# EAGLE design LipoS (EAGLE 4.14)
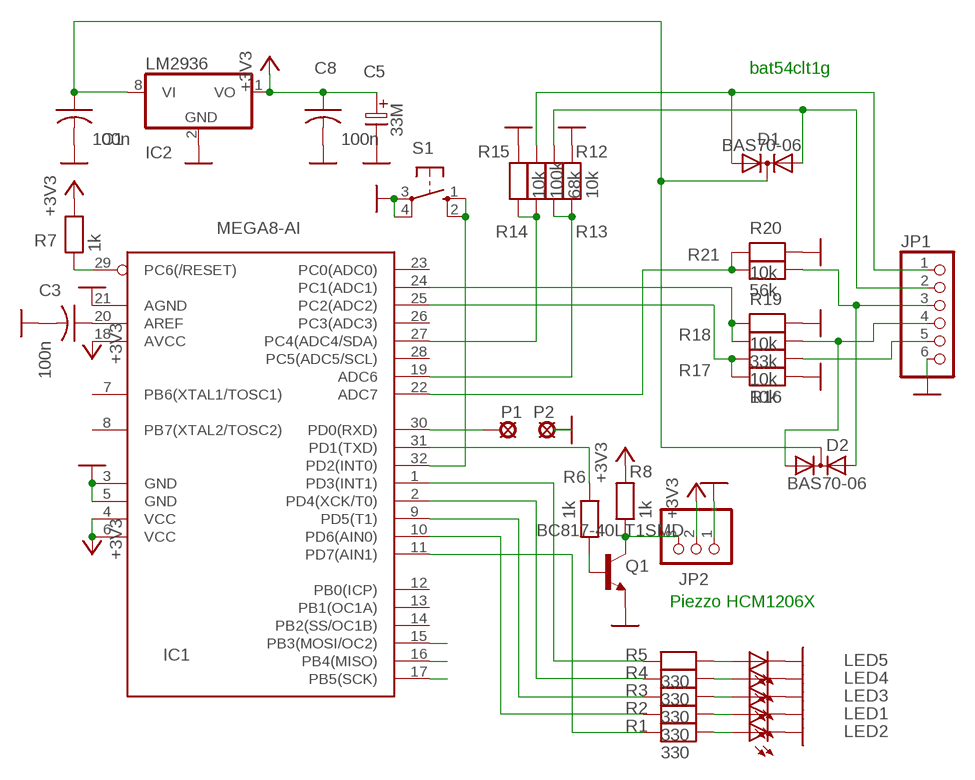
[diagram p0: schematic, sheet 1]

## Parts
C1  100n  CAP-50805  [C0805K]
C3  100n  CAP-50805  [C0805K]
C5  33M  ELC-2,5  [CAP_B]
C8  100n  CAP-50805  [C0805K]
D1  BAS70-06  [SOT23]
D2  BAS70-06  [SOT23]
IC1  MEGA8-AI  [TQFP32-08]
IC2  LM2936  LM2931  [SO08]
JP1  PINHD-1X6  [1X06]
JP2  PINHD-1X3  [1X03]
LED1  LEDCHIPLED_0805  [CHIPLED_0805]
LED2  LEDCHIPLED_0805  [CHIPLED_0805]
LED3  LEDCHIPLED_0805  [CHIPLED_0805]
LED4  LEDCHIPLED_0805  [CHIPLED_0805]
LED5  LEDCHIPLED_0805  [CHIPLED_0805]
P1  SMD  [SMD]
P2  SMD  [SMD]
Q1  BC817-40LT1SMD  [SOT23-BEC]
R1  330  RESEU-7,50805  [C0805K]
R2  330  RESEU-7,50805  [C0805K]
R3  330  RESEU-7,50805  [C0805K]
R4  330  RESEU-7,50805  [C0805K]
R5  330  RESEU-7,50805  [C0805K]
R6  1k  RESEU-7,50805  [C0805K]
R7  1k  RESEU-7,50805  [C0805K]
R8  1k  RESEU-7,50805  [C0805K]
R12  10k  RESEU-7,50805  [C0805K]
R13  68k  RESEU-7,50805  [C0805K]
R14  100k  RESEU-7,50805  [C0805K]
R15  10k  RESEU-7,50805  [C0805K]
R16  10k  RESEU-7,50805  [C0805K]
R17  10k  RESEU-7,50805  [C0805K]
R18  33k  RESEU-7,50805  [C0805K]
R19  10k  RESEU-7,50805  [C0805K]
R20  10k  RESEU-7,50805  [C0805K]
R21  56k  RESEU-7,50805  [C0805K]
S1  10-XX  [B3F-10XX]

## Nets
+3V3: C5.1 C8.1 IC1.4(VCC) IC1.6(VCC) IC1.18(AVCC) IC2.1(VO) JP2.2 R7.2 R8.2
GND: C1.2 C3.2 C5.2 C8.2 IC1.3(GND) IC1.5(GND) IC1.21(AGND) IC2.2(GND) JP1.6 JP2.1 LED1.C LED2.C LED3.C LED4.C LED5.C P2.1(MP) Q1.E R12.2 R15.2 R16.2 R19.2 R20.2 S1.3(P) S1.4(P1)
MISO: IC1.16(PB4(MISO))
MOSI: IC1.15(PB3(MOSI/OC2))
N$1: LED1.A R2.2
N$3: IC1.2(PD4(XCK/T0)) R4.1
N$4: LED3.A R3.2
N$5: LED2.A R1.2
N$6: LED4.A R4.2
N$7: LED5.A R5.2
N$8: IC1.9(PD5(T1)) R3.1
N$9: IC1.10(PD6(AIN0)) R2.1
N$10: C3.1 IC1.20(AREF)
N$11: IC1.11(PD7(AIN1)) R1.1
N$12: JP2.3 Q1.C R8.1
N$13: Q1.B R6.2
N$35: IC1.32(PD2(INT0)) S1.1(S) S1.2(S1)
P1: IC1.1(PD3(INT1)) R5.1
RST: IC1.29(PC6(/RESET)) R7.1
RXD: IC1.30(PD0(RXD)) P1.1(MP)
SCK: IC1.17(PB5(SCK))
TXD: IC1.31(PD1(TXD)) R6.1
U1: JP1.5 R17.2
U2: D2.1(A1) JP1.4 R18.2
U3: D2.2(A2) JP1.3 R21.2
U4: D1.1(A1) JP1.2 R13.2
U5: D1.2(A2) JP1.1 R14.2
UD1: IC1.25(PC2(ADC2)) R16.1 R17.1
UD2: IC1.24(PC1(ADC1)) R18.1 R19.1
UD3: IC1.22(ADC7) R20.1 R21.1
UD4: IC1.19(ADC6) R12.1 R13.1
UD5: IC1.27(PC4(ADC4/SDA)) R14.1 R15.1
VIN: C1.1 D1.3(C) D2.3(C) IC2.8(VI)
Unconnected: IC1.7(PB6(XTAL1/TOSC1)) IC1.8(PB7(XTAL2/TOSC2)) IC1.12(PB0(ICP)) IC1.13(PB1(OC1A)) IC1.14(PB2(SS/OC1B)) IC1.23(PC0(ADC0)) IC1.26(PC3(ADC3)) IC1.28(PC5(ADC5/SCL))

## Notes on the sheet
- bat54clt1g
- Piezzo HCM1206X

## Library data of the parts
C1 C3 C8 = discrete:CAP-5
C5 = discrete:ELC-2,5
D1 D2 = diode:BAS70-06: Silicon Schottky Diodes General-purpose diode for high-speed switching
IC1 = avr:MEGA8: MICROCONTROLLER 8 Kbytes FLASH 1 kbytes SRAM 512 bytes EEPROM USART 6-channel 10 bit ADC 2-channel 8 bit ADC
IC2 = linear:LM2931
JP1 = pinhead:PINHD-1X6: PIN HEADER
JP2 = pinhead:PINHD-1X3: PIN HEADER
LED1-LED5 = led:LED: LED
P1 P2 = solpad:SMD
Q1 = transistor-npn:BC817*: NPN Transistor
R1-R8 R12-R21 = discrete:RESEU-7,5
S1 = switch-omron:10-XX: OMRON SWITCH

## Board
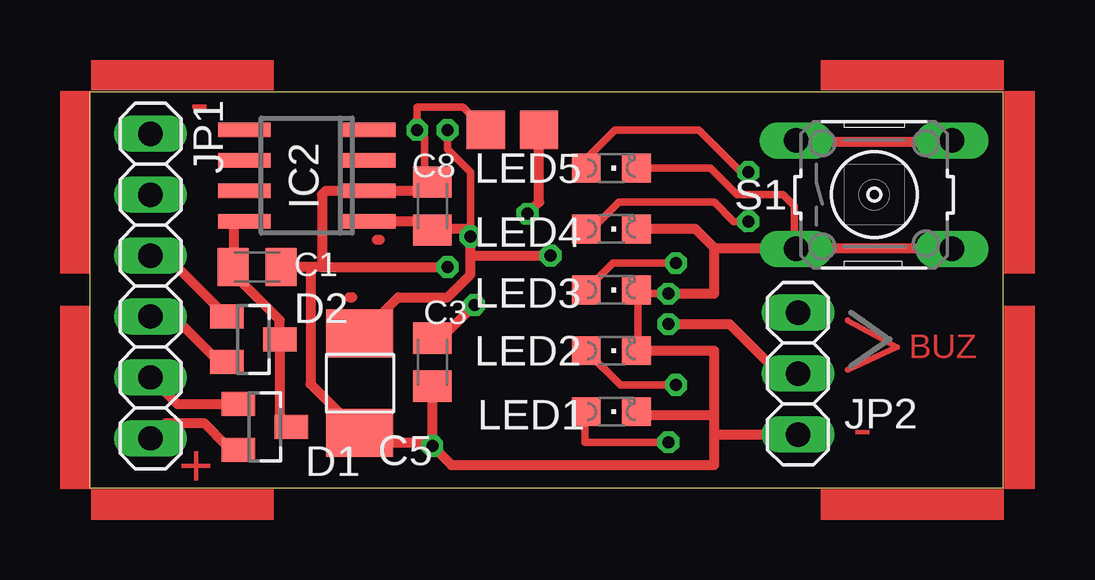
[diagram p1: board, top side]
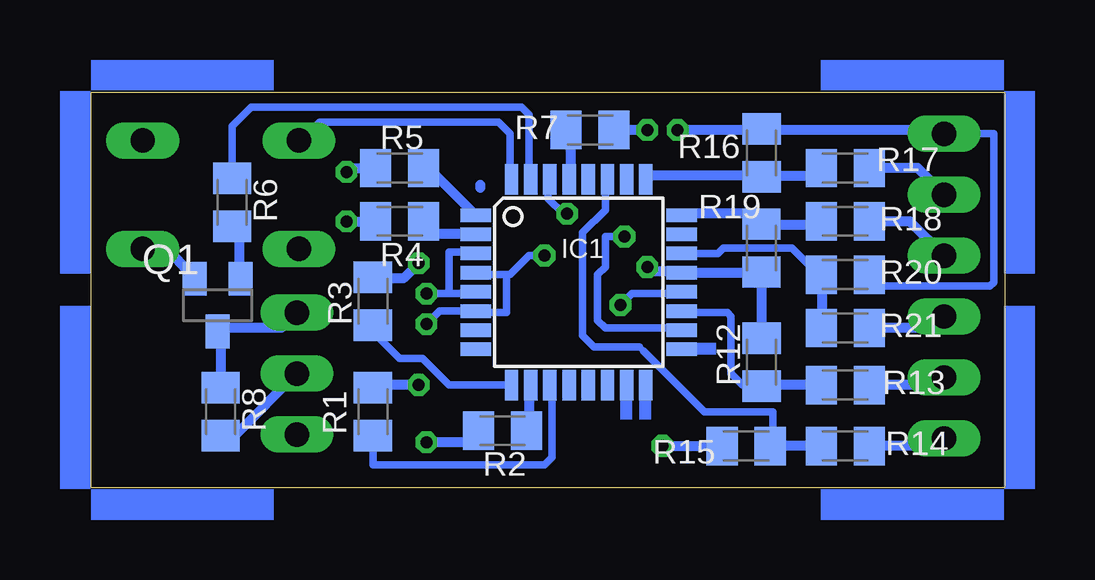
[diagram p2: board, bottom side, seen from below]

Size 38.09 x 16.5 mm. Coordinates in mm from the lower left corner, seen from the top.
Outline: 0,0 38.09,0 38.09,16.5 0,16.5 0,0
Copper layers (1*16): Top 0.035mm / dielectric 1.5mm / Bottom 0.035mm
Design rules "default": minimum track width 10mil, minimum drill 24mil, track to track 8mil, track to pad 8mil, pad to pad 8mil, via to via 8mil, smd to smd 8mil, copper to edge 40mil, drill to drill 8mil, minimum pad ring 10mil, minimum via ring 8mil, stop-mask expansion 0mil, vias tented up to drill 0mil, thermal gap 10mil

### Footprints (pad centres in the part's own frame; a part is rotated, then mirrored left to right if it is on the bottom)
C0805K = smd 1.3 x 1.6: 1 -1,0; 2 1,0
CAP_B = smd 2 x 2.8: 1 -2.155,-0.498; 2 1.998,-0.498
SOT23 = smd 1 x 1.4: 1 -0.95,-1.1; 2 0.95,-1.1; 3 0,1.1
TQFP32-08 = smd 1.27 x 0.559: 1 -4.293,2.8; 2 -4.293,2; 3 -4.293,1.2; 4 -4.293,0.4; 5 -4.293,-0.4; 6 -4.293,-1.2; 7 -4.293,-2; 8 -4.293,-2.8; 17 4.293,-2.8; 18 4.293,-2; 19 4.293,-1.2; 20 4.293,-0.4; 21 4.293,0.4; 22 4.293,1.2; 23 4.293,2; 24 4.293,2.8 | smd 0.559 x 1.27: 9 -2.8,-4.293; 10 -2,-4.293; 11 -1.2,-4.293; 12 -0.4,-4.293; 13 0.4,-4.293; 14 1.2,-4.293; 15 2,-4.293; 16 2.8,-4.293; 25 2.8,4.293; 26 2,4.293; 27 1.2,4.293; 28 0.4,4.293; 29 -0.4,4.293; 30 -1.2,4.293; 31 -2,4.293; 32 -2.8,4.293
SO08 = smd 0.6 x 2.2: 1 -1.905,-2.6; 2 -0.635,-2.6; 3 0.635,-2.6; 4 1.905,-2.6; 5 1.905,2.6; 6 0.635,2.6; 7 -0.635,2.6; 8 -1.905,2.6
1X06 = drill 1.016 long: 1 -6.35,0; 2 -3.81,0; 3 -1.27,0; 4 1.27,0; 5 3.81,0; 6 6.35,0
1X03 = drill 1.016 long: 1 -2.54,0; 2 0,0; 3 2.54,0
CHIPLED_0805 = smd 1.2 x 1.2: A 0,-1.05; C 0,1.05
SMD = smd 1.6 x 1.6: 1 0,0
SOT23-BEC = smd 1 x 1.4: B -0.95,-1.1; C 0,1.1; E 0.95,-1.1
B3F-10XX = drill 1.016 long: 1 -3.251,2.261; 2 3.251,2.261; 3 -3.251,-2.261; 4 3.251,-2.261

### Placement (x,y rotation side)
C1  6.98,9.2 0 top
C3  14.28,5.23 270 top
C5  11.74,4.28 270 top
C8  14.28,11.74 90 top
D1  7.3,2.54 270 top
D2  6.82,6.19 270 top
IC1  17.77,8.57 0 bottom
IC2  9.04,13.01 90 top
JP1  2.53,8.41 90 top
JP2  29.52,4.76 90 top
LED1  21.74,3.17 270 top
LED2  21.74,5.71 270 top
LED3  21.74,8.25 270 top
LED4  21.74,10.79 270 top
LED5  21.74,13.33 270 top
P1  18.73,14.92 90 top
P2  16.5,14.92 0 top
Q1  32.82,7.62 180 bottom
R1  26.35,3.17 90 bottom
R2  20.95,2.38 180 bottom
R3  26.35,7.77 90 bottom
R4  25.23,11.11 180 bottom
R5  25.23,13.33 180 bottom
R6  32.22,11.9 270 bottom
R7  17.3,14.92 0 bottom
R8  32.7,3.17 270 bottom
R12  10.15,5.23 90 bottom
R13  6.66,4.28 0 bottom
R14  6.66,1.74 0 bottom
R15  10.79,1.74 180 bottom
R16  10.15,13.96 90 bottom
R17  6.66,13.33 0 bottom
R18  6.66,11.11 0 bottom
R19  10.15,10 270 bottom
R20  6.66,8.89 0 bottom
R21  6.66,6.66 0 bottom
S1  32.7,12.22 0 top
U$9  [ANGLE-NE1-16]  38.13,16.57 0 top
U$10  [ANGLE-NE1-16]  0.03,16.57 90 top
U$12  [ANGLE-NE1-16]  0.03,-0.07 180 top
U$13  [ANGLE-NE1-16]  38.13,-0.07 270 top

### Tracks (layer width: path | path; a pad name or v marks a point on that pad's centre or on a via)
+3V3  (via drill 0.5)
  Top 0.305: v14.92,14.92 14.92,14.12 15.87,13.17 15.87,10.79 v15.87,10.47 | 14.33,10.79 C8.1 14.12,10.9 14.12,11.11 | C5.1 11.36,6.44 | JP2.2
  Top 0.406: 15.87,9.68 15.87,8.88 14.92,7.93 12.85,7.93 11.36,6.44 | 15.87,9.68 v15.87,10.47 | v24.12,6.82 26.66,6.82 28.73,4.76 JP2.2 | 15.87,9.68 v19.2,9.68 | 15.87,10.79 14.33,10.79 | 14.12,11.11 IC2.1
  Bottom 0.254: 22,7.3 IC1.6 | IC1.4 22.06,9.04
  Bottom 0.305: IC1.18 13.58,6.66 16.66,6.66 16.98,6.98 16.98,8.88 16.66,9.2 16.66,10.47 v15.87,10.47 | R8.2 32.7,2.22 32.06,2.22 | IC1.6 23.58,7.37 v24.12,6.82 | 22,7.3 20.79,7.3 20.79,8.88 | 20.79,8.88 21.9,8.88 21.9,8.97 IC1.4 22.07,8.89 22.06,8.88 IC1.4 | 20.79,8.88 20.63,8.88 19.84,9.68 v19.2,9.68 | R7.2
  Bottom 0.406: JP2.2 32.06,2.22 | v14.92,14.92 R7.2
GND  (via drill 0.5)
  Top 0.305: LED5.C 25.87,13.33 26.98,12.22 28.89,12.22 29.36,11.74 29.36,10 | LED2.C 22.85,5.71 22.85,8.19 LED3.C | LED2.C | LED3.C 22.95,8.09 v24.12,8.09 22.7,8.09 22.7,8.15 LED3.C | 22.85,3.01 22.85,3.11 LED1.C | 11.58,1.9 11.58,1.94 C5.2 | 14.12,1.9 v14.28,1.74 | 14.28,4.55 C3.2 | 29.36,10 29.41,10 S1.3 | 36.03,10 35.99,10 S1.4 | S1.3 29.48,10 | 26.03,3.01 26.03,2.22 | IC2.2 11.42,12.38 | P2.1 15.55,15.87 13.65,15.87 v13.65,14.92 13.96,14.6 13.96,12.85 14.17,12.85 C8.2 13.96,12.43 13.96,12.38 | 29.36,10 29.4,9.96 S1.3 | LED4.C | JP2.1 | C1.2
  Top 0.406: 22.85,5.71 26.03,5.71 26.03,3.01 | 26.03,3.01 22.85,3.01 | 11.58,1.9 14.12,1.9 | 14.28,4.55 v14.28,1.74 15.08,0.95 26.03,0.95 26.03,3.01 | 29.48,10 35.99,10 | 26.03,2.22 JP2.1 | 9.2,9.2 C1.2 | 9.68,9.2 9.2,9.2 | 9.68,9.2 v14.92,9.2 | C5.2 9.2,4.33 9.2,9.2 | 26.03,10 29.36,10 | LED4.C 25.24,10.79 26.03,10 | 26.03,10 26.03,8.09 v24.12,8.09 | 13.96,12.38 IC2.2 9.84,12.38 9.68,12.22 9.68,9.2
  Bottom 0.305: 10.15,14.92 R16.2 | JP1.6 2.69,14.92 | R20.2 5.19,8.41 0.63,8.41 0.47,8.57 0.47,14.76 JP1.6 | JP1.6 | v24.12,8.09 23.17,8.09 | 23.17,8.09 22.14,8.09 IC1.5 22.06,8.16 22.06,8.09 23.17,8.09 | IC1.3 22.14,9.84 23.17,9.84 23.17,8.09 | R15.2 | 36.03,10 35.99,10 S1.4 | 10.15,6.19 R12.2 | 10.15,6.19 | R19.2 10.2,9 10.31,8.88 10.4,8.97 | 13.49,9.04 IC1.21 | v14.92,9.2 14.76,9.04
  Bottom 0.406: 2.69,14.92 10.15,14.92 v13.65,14.92 | v14.28,1.74 R15.2 | Q1.E 34.93,10 35.99,10 | R19.2 10.15,6.19 | IC1.21 10.4,8.97 | 14.76,9.04 13.49,9.04
N$1  (via drill 0.5)
  Top 0.305: v24.12,1.9 20.63,1.9 20.63,3.11 LED1.A
  Bottom 0.305: R2.2 22.43,1.9
  Bottom 0.406: 22.43,1.9 v24.12,1.9
N$2
  Bottom 0.406: 21.87,12.5 21.87,12.63
N$3
  Bottom 0.406: R4.1 24.23,10.9 23.9,10.57 IC1.2
N$4  (via drill 0.5)
  Top 0.305: LED3.A 21.8,9.36 v24.44,9.36
  Bottom 0.305: 26.35,8.73 R3.2 | R3.2
  Bottom 0.406: v24.44,9.36 25.08,8.73 26.35,8.73
N$5  (via drill 0.5)
  Top 0.305: LED2.A 22.12,4.28 v24.44,4.28
  Bottom 0.305: 26.35,4.28 R1.2 | R1.2
  Bottom 0.406: v24.44,4.28 26.35,4.28
N$6  (via drill 0.5)
  Top 0.305: LED4.A 20.79,10.89 20.79,10.95 21.11,10.95 22.06,11.9 26.03,11.9 26.82,11.11 v27.46,11.11
  Bottom 0.305: R4.2
  Bottom 0.406: v27.46,11.11 R4.2
N$7  (via drill 0.5)
  Top 0.305: LED5.A 20.69,13.71 21.9,14.92 25.39,14.92 27.14,13.17 v27.46,13.17
  Bottom 0.305: R5.2 26.19,13.33 | R5.2 | v27.46,13.17 27.3,13.33
  Bottom 0.406: 27.3,13.33 R5.2
N$8
  Bottom 0.305: IC1.9 23.17,4.28 24.28,5.39 25.24,5.39 26.35,6.5 R3.1
N$9
  Bottom 0.305: 19.84,4.28 IC1.10 | 19.84,2.49 R2.1
  Bottom 0.406: 19.84,4.28 19.84,2.49
N$10  (via drill 0.5)
  Top 0.305: C3.1 14.65,6.23
  Top 0.406: 14.65,6.23 v16.03,7.61
  Bottom 0.305: IC1.20 13.56,8.09 15.55,8.09 v16.03,7.61
N$11
  Bottom 0.305: IC1.11 18.89,4.19 18.89,1.26 19.2,0.95 26.35,0.95 R1.1 | R1.1 26.35,2.38 | R1.1
N$12
  Bottom 0.305: 32.55,6.66 Q1.C 32.7,6.51 | R8.1 32.7,4.12
  Bottom 0.406: JP2.3 30.16,6.66 32.55,6.66 | 32.7,6.51 R8.1
N$13
  Bottom 0.305: 31.9,8.73 31.76,8.73 Q1.B | 31.9,10.58 R6.2
  Bottom 0.406: 31.9,8.73 31.9,10.58
N$16
  Top 0.254: 31.58,6.98 33.65,5.87 31.58,4.92
N$17
  Top 0.406: 11.96,10.35 12.09,10.35
N$18
  Top 0.406: 10.82,7.93 10.95,7.93
N$35
  Top 0.305: 36.03,14.44 35.99,14.44 S1.2 | S1.1 29.48,14.44
  Top 0.406: 29.48,14.44 35.99,14.44
  Bottom 0.305: IC1.32 20.63,12.92 20.63,14.76 21.11,15.24 28.57,15.24 29.2,14.6 29.36,14.6 29.36,14.56 S1.1
P1
  Bottom 0.305: R5.1 | 24.03,13.33 R5.1
  Bottom 0.406: IC1.1 24.03,13.33
RST
  Bottom 0.305: 18.09,14.65 R7.1 | IC1.29 18.09,12.94
  Bottom 0.406: 18.09,12.94 18.09,14.65
RXD  (via drill 0.5)
  Top 0.406: P1.1 18.73,11.9 v18.25,11.43
  Bottom 0.305: IC1.30 19.04,12.79 19.04,12.06 18.41,11.43 v18.25,11.43
TXD
  Bottom 0.305: IC1.31 19.84,12.92 19.84,15.55 20.15,15.87 31.43,15.87 32.22,15.08 R6.1 | R6.1 32.22,12.7 | R6.1
U1
  Bottom 0.406: JP1.5 3.64,13.33 R17.2
U2
  Top 0.305: D2.1 | 2.69,9.68
  Top 0.406: D2.1 3.17,9.68 2.69,9.68 JP1.4
  Bottom 0.305: R18.2 5.71,11.11 | R18.2
  Bottom 0.406: JP1.4 3.96,11.11 R18.2
U3
  Top 0.305: D2.2 5.39,5.24 | 2.69,7.14
  Top 0.406: 5.39,5.24 3.49,7.14 2.69,7.14 JP1.3
  Bottom 0.305: R21.2 5.71,6.66 | R21.2
  Bottom 0.406: JP1.3 3.01,6.66 R21.2
U4
  Top 0.305: JP1.2
  Top 0.406: D1.1 3.65,3.49 JP1.2
  Bottom 0.406: JP1.2 2.85,4.28 R13.2
U5
  Top 0.305: D1.2 6.04,1.74 5.71,1.74
  Top 0.406: JP1.1 3.17,2.69 4.76,2.69 5.71,1.74
  Bottom 0.305: R14.2 5.71,1.74 | R14.2
  Bottom 0.406: JP1.1 2.85,1.74 R14.2
UD1
  Bottom 0.305: 10.15,13.01 R16.1 10.2,13.01 | 7.98,13.01 R17.1 | 14.82,13.01 IC1.25
  Bottom 0.406: 10.15,13.01 7.98,13.01 | 10.2,13.01 14.82,13.01
UD2
  Bottom 0.305: R18.1 7.82,10.95 | 13.42,11.43 IC1.24 | R19.1 10.15,10.95 10.63,11.43 | R19.1
  Bottom 0.406: 7.82,10.95 10.15,10.95 | 10.63,11.43 13.42,11.43
UD3
  Bottom 0.254: R21.1 7.61,6.71 | 7.61,8.84 R20.1
  Bottom 0.305: IC1.22 11.97,9.77 11.74,10 8.88,10 7.93,9.04 7.77,9.04 7.77,9 R20.1
  Bottom 0.406: 7.61,6.71 7.61,8.84
UD4
  Bottom 0.305: R13.1 7.61,4.28 | 10.11,4.28 R12.1 10.2,4.28 10.95,4.28 11.42,4.76 11.42,7.14 11.58,7.3 13.49,7.3 13.48,7.3 IC1.19 13.41,7.3
  Bottom 0.406: R13.1 10.11,4.28
UD5
  Bottom 0.254: 15.07,5.71 15.23,5.87 | 16.66,12.85 IC1.27
  Bottom 0.305: 16.66,12.77 IC1.27 16.57,12.78 16.66,12.7 16.66,11.58 17.61,10.63 17.61,6.34 17.14,5.87 15.23,5.87 | 15.07,5.71 12.53,3.17 9.68,3.17 9.68,1.74 R15.1 | R15.1 | R14.1
  Bottom 0.406: R14.1 9.68,1.74
VIN
  Top 0.305: 7.93,6.5 7.92,6.5 D2.3 | D1.3 7.93,3.02 | C1.1 6.03,9.2 | C1.1 | 6.03,11.01 IC2.8 | C1.1 5.98,9.09 6.34,8.73 6.34,8.57
  Top 0.406: 7.93,3.02 7.93,6.5 | 6.03,9.2 6.03,11.01 | 7.92,6.5 7.92,6.99 6.34,8.57
(copper drawn outside any net)
  shapes: Bottom area x3

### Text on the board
Top: - | BUZ | - | +
Document: PACK | GND | 3.2 | 1 | Clanek 1 | 3.0 | 2 | Clanek 2 | 2.8 | 3 | Clanek 3 | BUZ | 2.6 | 4 | Clanek 4 | 2.4 | 5 | GND | Clanek 5 | VOLTAGE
